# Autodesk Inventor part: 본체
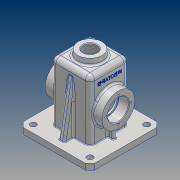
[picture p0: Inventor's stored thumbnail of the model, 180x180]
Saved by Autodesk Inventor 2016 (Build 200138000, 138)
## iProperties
Created: 2018-10
Part Number: 본체
Material: 알루미늄 6061
Document SubType Name: Modeling
Designer: user
Density: 2.7 g/cm^3
Appearance: 알루미늄 - 평지
Mass: 794.228 g
Surface Area: 899.5 cm^2
Volume: 294.158 cm^3
Author: user
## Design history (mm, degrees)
sketch "스케치1"
  geometry: L1 (-32.5, -32.5)-(32.5, -32.5); L2 (32.5, -32.5)-(32.5, 32.5); L3 (32.5, 32.5)-(-32.5, 32.5); L4 (-32.5, 32.5)-(-32.5, -32.5); L5 (-32.5, -32.5)-(32.5, 32.5); L6 (32.5, -32.5)-(-32.5, 32.5); 1 further point
  constraints: 12 end point, 2 midpoint, 2 parallel, 1 horizontal, 1 perpendicular
  dimensions: "d0" = 65 distance of L3.end L2.end; "d1" = 65 distance of L2.end L1.end
extrude "돌출1" new body sketch "스케치1" distance "d2" = 100; taper "d3" = 0 deg
sketch "스케치2"
  geometry: L1 (60, -60)-(-60, -60); L2 (-60, -60)-(-60, 60); L3 (-60, 60)-(60, 60); L4 (60, 60)-(60, -60); L5 (60, -60)-(-60, 60); L6 (-60, -60)-(60, 60); 1 further point
  constraints: 12 end point, 2 midpoint, 2 parallel, 1 horizontal, 1 perpendicular
  dimensions: "d4" = 120 distance of L2.end L3.end; "d5" = 120 distance of L1.end L2.end
extrude "돌출2" join sketch "스케치2" distance "d6" = 10; taper "d7" = 0 deg
node "작업 평면1"
feature "쉘1" dims "d27" = 10, "d28" = 5
sketch "스케치4"
  geometry: L1 (110, 92.5)-(110, -27.5) reference; C1 r 27.5 at (55, 32.5); 1 further point
  constraints: 1 centre point
  dimensions: "d12" = 55 diameter of C1; "d13" = 55 distance from line of L1 C1.centre
extrude "돌출4" join sketch "스케치4" distance "d14" = 15; taper "d15" = 0 deg
sketch "스케치5"
  geometry: C1 r 27.5 at (0, 0) reference; 2 further points
  constraints: 1 horizontal alignment
  dimensions: "d16" = 21 distance of C1.centre point (-21, 0)
hole "구멍1" sketch "스케치5" at (-21, 0) diameter "d17" = 3.242; stored, may be unused: countersink angle "d21" = 90 deg, drill point angle "d23" = 118 deg; dims "d18" = 8, "d19" = 4, "d20" = 2, "d22" = 10
hole "구멍2" diameter "d31" = 30; stored, may be unused: countersink angle "d35" = 90 deg, drill point angle "d37" = 0 deg; dims "d29" = 10, "d30" = 10, "d32" = 8, "d33" = 35, "d34" = 17, "d36" = 10
node "작업 평면2"
sketch "스케치6"
  geometry: L1 (0, 92.5)-(0, 120) reference; L2 (0, 120)-(10, 120) reference; L3 (10, 120)-(10, 87.5) reference; L4 (10, 87.5)-(-95, 87.5) reference; L5 (-95, 87.5)-(-95, 32.5) reference; L6 (-95, 32.5)-(10, 32.5) reference; L7 (10, 32.5)-(10, 0) reference; L8 (10, 0)-(0, 0) reference; L9 (0, 0)-(0, 27.5) reference; L10 (0, 27.5)-(-100, 27.5) reference; L11 (-100, 27.5)-(-100, 92.5) reference; L12 (-100, 92.5)-(0, 92.5) reference; L13 (0, 120)-(0, 0) reference; L14 (0, 108)-(-87.905, 92.5); L15 (0, 12)-(-87.905, 27.5); L16 (0, 27.5)-(-100, 27.5) reference; 1 further point
  constraints: 4 end point, 4 point on line
  dimensions: "d38" = 12 distance from line of L2 L14.start; "d39" = 12 distance from line of L8 L15.start; "d40" = 10 deg angle of L8 L15; "d41" = 10 deg angle of L2 L14
  node "절단 모서리 투영1"
feature "리브1" dims "d42" = 1, "d43" = 10, "d44" = 0, "d45" = 0, "d46" = 1, "d47" = 1
feature "리브2" dims "d48" = 1, "d49" = 10, "d50" = 0, "d51" = 0, "d52" = 1, "d53" = 1
sketch "스케치7"
  geometry: L1 (32.5, -32.5)-(32.5, 32.5) reference; L2 (32.5, 3)-(42.5, 3); L3 (42.5, 3)-(42.5, -3); L4 (42.5, -3)-(32.5, -3); L5 (32.5, 3)-(32.5, -3); 2 further points
  constraints: 8 end point, 2 perpendicular, 2 point on line, 1 collinear, 1 horizontal, 1 horizontal alignment, 1 midpoint
  dimensions: "d54" = 10 distance of L2.start L2.end; "d55" = 6 distance of L2.end L3.end
extrude "돌출5" join sketch "스케치7" stored distance "d56" = 15; taper "d57" = 0 deg
sketch "스케치8"
  geometry: L1 (47.5, -47.5)-(-47.5, -47.5); L2 (-47.5, -47.5)-(-47.5, 47.5); L3 (-47.5, 47.5)-(47.5, 47.5); L4 (47.5, 47.5)-(47.5, -47.5); L5 (47.5, -47.5)-(-47.5, 47.5); L6 (-47.5, -47.5)-(47.5, 47.5); 5 further points
  constraints: 12 end point, 4 coincident, 2 midpoint, 2 parallel, 1 horizontal, 1 perpendicular
  dimensions: "d58" = 95 distance of L2.end L3.end; "d59" = 95 distance of L1.end L2.end
hole "구멍3" sketch "스케치8" at (-47.5, -47.5), (-47.5, 47.5), (47.5, 47.5), (47.5, -47.5) diameter "d60" = 10; stored, may be unused: countersink angle "d64" = 90 deg, drill point angle "d66" = 0 deg; dims "d61" = 8, "d62" = 35, "d63" = 17, "d65" = 10
node "작업 평면3"
sketch "스케치9"
  geometry: C1 r 20 at (0, 0); 1 further point
  constraints: 1 centre point, 1 coincident
  dimensions: "d68" = 40 diameter of C1
extrude "돌출6" join sketch "스케치9" stored distance "d69" = 15; taper "d70" = 7 deg
hole "구멍4" diameter "d73" = 22.835; stored, may be unused: countersink angle "d77" = 90 deg, drill point angle "d79" = 0 deg; dims "d71" = 10, "d72" = 10, "d74" = 50, "d75" = 35, "d76" = 17, "d78" = 59.3
chamfer "모따기1" distance "d80" = 8; stored, may be unused: second distance "d81" = 2, angle "d82" = 45 deg
sketch "스케치10"
  geometry: L1 (100, 0)-(0, 0) reference; L2 (-10, 52.5)-(-10, 12.5) reference; 2 further points
  constraints: 1 other
  dimensions: "d83" = 26 distance from line of L2 point (16, 32.5); "d84" = 32.5 distance from line of L1 point (16, 32.5)
feature "엠보싱1" sketch "스케치10" dims "d12" = 55, "d85" = 0.5, "d86" = 0
fillet "모깎기1" dims "d87" = 8
fillet "모깎기2" dims "d88" = 8
fillet "모깎기3" dims "d89" = 3
fillet "모깎기4" dims "d90" = 3
fillet "모깎기5" dims "d91" = 3
fillet "모깎기6" dims "d92" = 3
fillet "모깎기7" dims "d93" = 3
fillet "모깎기8" dims "d94" = 1
chamfer "모따기2" distance "d95" = 1; stored, may be unused: second distance "d96" = 2, angle "d97" = 45 deg
fillet "모깎기9" dims "d98" = 0.3
node "솔리드1"
pattern_circular "원형 패턴1" dims angle "d25" = 360 deg
mirror "대칭1"
mirror "대칭2"
